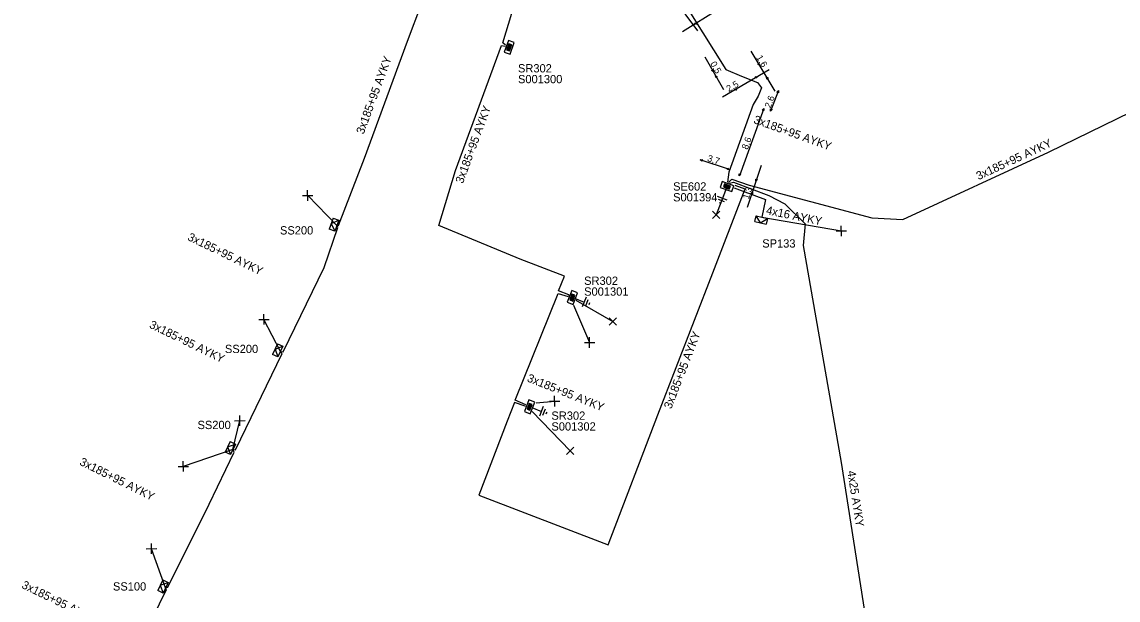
# Model space of a CAD drawing. Extents: x -762500 to -761285, y -1155006 to -1154135.
# Drawn here: x -762041.4 to -761909.8, y -1154932.9 to -1154863.6 of the extents above; entities that cross this region are included whole.
import ezdxf

# ---------------------------------------------------------------- set-up
doc = ezdxf.new("R2010")
doc.units = 0
for name, color, linetype in [('Vrstva 15', 7, 'Continuous'), ('Vrstva 28', 7, 'Continuous'), ('Vrstva 29', 7, 'Continuous'), ('Vrstva 30', 7, 'Continuous'), ('Vrstva 31', 7, 'Continuous'), ('Vrstva 33', 7, 'Continuous'), ('Vrstva 34', 7, 'Continuous'), ('Vrstva 40', 7, 'Continuous'), ('Vrstva 5', 7, 'Continuous'), ('Vrstva 59', 7, 'Continuous'), ('Vrstva 6', 7, 'Continuous')]:
    doc.layers.add(name, color=color, linetype=linetype)

msp = doc.modelspace()

# ---------------------------------------------------------------- linework, layer by layer
at = {"layer": 'Vrstva 15'}
for points in [[(-761956.7, -1154884.95), (-761957.867, -1154884.502)], [(-761956.836, -1154883.559), (-761957.284, -1154884.726)], [(-761957.036, -1154885.153), (-761957.771, -1154884.871)], [(-761957.508, -1154885.31), (-761957.627, -1154885.264)], [(-761957.383, -1154885.357), (-761957.508, -1154885.31)], [(-761975.04, -1154896.716), (-761973.873, -1154897.164)], [(-761973.649, -1154896.58), (-761974.097, -1154897.747)], [(-761973.446, -1154896.916), (-761973.729, -1154897.652)], [(-761973.29, -1154897.388), (-761973.336, -1154897.507)], [(-761973.242, -1154897.264), (-761973.29, -1154897.388)], [(-761980.171, -1154909.826), (-761979.004, -1154910.274)], [(-761978.78, -1154909.69), (-761979.228, -1154910.857)], [(-761978.577, -1154910.026), (-761978.859, -1154910.762)], [(-761978.42, -1154910.498), (-761978.466, -1154910.617)], [(-761978.373, -1154910.374), (-761978.42, -1154910.498)]]:
    msp.add_lwpolyline(points, dxfattribs=at)
at = {"layer": 'Vrstva 28'}
for points in [[(-761982.966, -1154865.772), (-761983.479, -1154867.181)], [(-761982.262, -1154866.028), (-761982.966, -1154865.772)], [(-761982.775, -1154867.438), (-761982.262, -1154866.028)], [(-761983.479, -1154867.181), (-761982.775, -1154867.438)], [(-761982.925, -1154866.195), (-761983.18, -1154866.894)], [(-761983.18, -1154866.894), (-761982.825, -1154867.023)], [(-761982.897, -1154866.255), (-761983.119, -1154866.866)], [(-761983.119, -1154866.866), (-761982.853, -1154866.963)], [(-761982.869, -1154866.316), (-761983.059, -1154866.838)], [(-761983.059, -1154866.838), (-761982.881, -1154866.902)], [(-761982.841, -1154866.377), (-761982.998, -1154866.809)], [(-761982.998, -1154866.809), (-761982.91, -1154866.842)], [(-761982.94, -1154866.787), (-761982.811, -1154866.432)], [(-761982.57, -1154866.324), (-761982.925, -1154866.195)], [(-761982.91, -1154866.842), (-761982.752, -1154866.409)], [(-761982.631, -1154866.352), (-761982.897, -1154866.255)], [(-761982.881, -1154866.902), (-761982.691, -1154866.381)], [(-761982.691, -1154866.381), (-761982.869, -1154866.316)], [(-761982.853, -1154866.963), (-761982.631, -1154866.352)], [(-761982.752, -1154866.409), (-761982.841, -1154866.377)], [(-761982.825, -1154867.023), (-761982.57, -1154866.324)], [(-761957.312, -1154882.701), (-761957.568, -1154883.406)], [(-761955.902, -1154883.214), (-761957.312, -1154882.701)], [(-761957.025, -1154883.001), (-761957.154, -1154883.356)], [(-761956.996, -1154883.061), (-761957.093, -1154883.327)], [(-761956.968, -1154883.122), (-761957.033, -1154883.299)], [(-761956.325, -1154883.255), (-761957.025, -1154883.001)], [(-761956.386, -1154883.283), (-761956.996, -1154883.061)], [(-761956.94, -1154883.182), (-761956.972, -1154883.271)], [(-761956.446, -1154883.312), (-761956.968, -1154883.122)], [(-761956.507, -1154883.34), (-761956.94, -1154883.182)], [(-761957.568, -1154883.406), (-761956.159, -1154883.919)], [(-761957.154, -1154883.356), (-761956.455, -1154883.61)], [(-761957.093, -1154883.327), (-761956.483, -1154883.55)], [(-761957.033, -1154883.299), (-761956.511, -1154883.489)], [(-761956.972, -1154883.271), (-761956.539, -1154883.429)], [(-761956.917, -1154883.241), (-761956.562, -1154883.37)], [(-761956.539, -1154883.429), (-761956.507, -1154883.34)], [(-761956.511, -1154883.489), (-761956.446, -1154883.312)], [(-761956.483, -1154883.55), (-761956.386, -1154883.283)], [(-761956.455, -1154883.61), (-761956.325, -1154883.255)], [(-761956.159, -1154883.919), (-761955.902, -1154883.214)], [(-761975.374, -1154895.797), (-761975.911, -1154897.197)], [(-761975.341, -1154896.22), (-761975.607, -1154896.915)], [(-761975.313, -1154896.282), (-761975.546, -1154896.888)], [(-761975.286, -1154896.343), (-761975.485, -1154896.861)], [(-761974.674, -1154896.065), (-761975.374, -1154895.797)], [(-761974.988, -1154896.356), (-761975.341, -1154896.22)], [(-761975.049, -1154896.383), (-761975.313, -1154896.282)], [(-761975.11, -1154896.41), (-761975.286, -1154896.343)], [(-761975.211, -1154897.466), (-761974.674, -1154896.065)], [(-761975.911, -1154897.197), (-761975.211, -1154897.466)], [(-761975.607, -1154896.915), (-761975.254, -1154897.051)], [(-761975.546, -1154896.888), (-761975.282, -1154896.99)], [(-761975.485, -1154896.861), (-761975.309, -1154896.929)], [(-761975.259, -1154896.404), (-761975.424, -1154896.834)], [(-761975.424, -1154896.834), (-761975.336, -1154896.868)], [(-761975.365, -1154896.812), (-761975.23, -1154896.459)], [(-761975.336, -1154896.868), (-761975.171, -1154896.437)], [(-761975.309, -1154896.929), (-761975.11, -1154896.41)], [(-761975.282, -1154896.99), (-761975.049, -1154896.383)], [(-761975.171, -1154896.437), (-761975.259, -1154896.404)], [(-761975.254, -1154897.051), (-761974.988, -1154896.356)], [(-761980.504, -1154908.897), (-761981.041, -1154910.297)], [(-761980.47, -1154909.321), (-761980.737, -1154910.015)], [(-761980.443, -1154909.382), (-761980.676, -1154909.988)], [(-761980.416, -1154909.443), (-761980.615, -1154909.961)], [(-761980.389, -1154909.504), (-761980.554, -1154909.934)], [(-761979.803, -1154909.165), (-761980.504, -1154908.897)], [(-761980.117, -1154909.456), (-761980.47, -1154909.321)], [(-761980.178, -1154909.483), (-761980.443, -1154909.382)], [(-761980.239, -1154909.51), (-761980.416, -1154909.443)], [(-761980.411, -1154910.09), (-761980.178, -1154909.483)], [(-761980.301, -1154909.537), (-761980.389, -1154909.504)], [(-761980.384, -1154910.151), (-761980.117, -1154909.456)], [(-761980.341, -1154910.566), (-761979.803, -1154909.165)], [(-761981.041, -1154910.297), (-761980.341, -1154910.566)], [(-761980.737, -1154910.015), (-761980.384, -1154910.151)], [(-761980.676, -1154909.988), (-761980.411, -1154910.09)], [(-761980.615, -1154909.961), (-761980.438, -1154910.029)], [(-761980.554, -1154909.934), (-761980.466, -1154909.968)], [(-761980.495, -1154909.912), (-761980.359, -1154909.559)], [(-761980.466, -1154909.968), (-761980.301, -1154909.537)], [(-761980.438, -1154910.029), (-761980.239, -1154909.51)]]:
    msp.add_lwpolyline(points, dxfattribs=at)
at = {"layer": 'Vrstva 31'}
for points in [[(-762003.997, -1154887.09), (-762004.476, -1154888.406)], [(-762003.997, -1154887.09), (-762003.34, -1154887.329), (-762003.818, -1154888.645), (-762004.476, -1154888.406)], [(-761953.392, -1154887.489), (-761953.223, -1154886.81), (-761951.864, -1154887.149), (-761952.034, -1154887.828)], [(-761952.713, -1154887.659), (-761953.223, -1154886.81)], [(-762004.237, -1154887.748), (-762003.34, -1154887.329)], [(-762004.237, -1154887.748), (-762003.818, -1154888.645)], [(-761953.392, -1154887.489), (-761952.034, -1154887.828)], [(-761952.713, -1154887.659), (-761951.864, -1154887.149)], [(-762010.678, -1154902.167), (-762011.269, -1154903.436)], [(-762010.678, -1154902.167), (-762010.043, -1154902.463), (-762010.635, -1154903.731), (-762011.269, -1154903.436)], [(-762010.974, -1154902.801), (-762010.043, -1154902.463)], [(-762010.974, -1154902.801), (-762010.635, -1154903.731)], [(-762016.378, -1154913.897), (-762016.969, -1154915.166)], [(-762016.378, -1154913.897), (-762015.743, -1154914.193), (-762016.335, -1154915.461), (-762016.969, -1154915.166)], [(-762016.674, -1154914.531), (-762015.743, -1154914.193)], [(-762016.674, -1154914.531), (-762016.335, -1154915.461)], [(-762024.458, -1154930.497), (-762025.05, -1154931.766)], [(-762024.458, -1154930.497), (-762023.824, -1154930.793), (-762024.415, -1154932.062), (-762025.05, -1154931.766)], [(-762024.754, -1154931.131), (-762023.824, -1154930.793)], [(-762024.754, -1154931.131), (-762024.415, -1154932.062)]]:
    msp.add_lwpolyline(points, dxfattribs=at)
at = {"layer": 'Vrstva 34'}
for points in [[(-762007.685, -1154884.391), (-762006.435, -1154884.369)], [(-762007.049, -1154885.005), (-762007.071, -1154883.755)], [(-761958.472, -1154886.258), (-761957.588, -1154887.142)], [(-761958.472, -1154887.142), (-761957.588, -1154886.258)], [(-761942.989, -1154889.255), (-761943.011, -1154888.005)], [(-761943.625, -1154888.641), (-761942.375, -1154888.619)], [(-762012.299, -1154899.875), (-762012.321, -1154898.625)], [(-762012.935, -1154899.261), (-762011.685, -1154899.239)], [(-761970.882, -1154899.058), (-761969.998, -1154899.942)], [(-761970.882, -1154899.942), (-761969.998, -1154899.058)], [(-761973.219, -1154902.635), (-761973.241, -1154901.385)], [(-761973.855, -1154902.021), (-761972.605, -1154901.999)], [(-761978.035, -1154909.061), (-761976.785, -1154909.039)], [(-761977.399, -1154909.675), (-761977.421, -1154908.425)], [(-762015.199, -1154912.005), (-762015.221, -1154910.755)], [(-762015.835, -1154911.391), (-762014.585, -1154911.369)], [(-761976.002, -1154914.558), (-761975.118, -1154915.442)], [(-761976.002, -1154915.442), (-761975.118, -1154914.558)], [(-762022.625, -1154916.891), (-762021.375, -1154916.869)], [(-762021.989, -1154917.505), (-762022.011, -1154916.255)], [(-762025.799, -1154927.375), (-762025.821, -1154926.125)], [(-762026.435, -1154926.761), (-762025.185, -1154926.739)]]:
    msp.add_lwpolyline(points, dxfattribs=at)
at = {"layer": 'Vrstva 40'}
for points in [[(-761963.18, -1154860.67), (-761960.29, -1154864.64)], [(-761962.07, -1154864.73), (-761957.71, -1154862.01)], [(-761950.95, -1154871.87), (-761953.85, -1154867.09)], [(-761957.12, -1154871.71), (-761959.35, -1154867.81)], [(-761951.68, -1154869.31), (-761957.27, -1154872.57)], [(-761950.55, -1154871.8), (-761951.49, -1154874.25)], [(-761952.32, -1154873.93), (-761955.25, -1154882.04)], [(-761956.42, -1154881.26), (-761959.97, -1154880.09)], [(-761952.62, -1154880.77), (-761954.31, -1154885.83)]]:
    msp.add_lwpolyline(points, dxfattribs=at)
for points in [[(-761960.368, -1154863.669), (-761960.519, -1154863.892), (-761960.633, -1154863.717)], [(-761952.809, -1154868.802), (-761953.029, -1154868.647), (-761952.852, -1154868.536)], [(-761958.359, -1154869.552), (-761958.574, -1154869.389), (-761958.393, -1154869.285)], [(-761958.111, -1154869.978), (-761957.896, -1154870.141), (-761958.077, -1154870.245)], [(-761953.402, -1154870.321), (-761953.243, -1154870.104), (-761953.135, -1154870.283)], [(-761951.981, -1154870.167), (-761951.761, -1154870.323), (-761951.938, -1154870.433)], [(-761955.537, -1154871.559), (-761955.697, -1154871.777), (-761955.804, -1154871.598)], [(-761950.549, -1154871.798), (-761950.54, -1154872.068), (-761950.736, -1154871.993)], [(-761952.319, -1154873.928), (-761952.301, -1154874.197), (-761952.499, -1154874.129)], [(-761951.491, -1154874.252), (-761951.5, -1154873.982), (-761951.305, -1154874.057)], [(-761959.972, -1154880.089), (-761959.704, -1154880.066), (-761959.768, -1154880.265)], [(-761956.417, -1154881.261), (-761956.686, -1154881.283), (-761956.622, -1154881.085)], [(-761955.251, -1154882.042), (-761955.269, -1154881.773), (-761955.072, -1154881.841)], [(-761953.251, -1154882.672), (-761953.273, -1154882.404), (-761953.074, -1154882.468)], [(-761953.679, -1154883.938), (-761953.656, -1154884.207), (-761953.855, -1154884.142)]]:
    msp.add_lwpolyline(points, close=True, dxfattribs=at)
at = {"layer": 'Vrstva 5'}
for points in [[(-761983.32, -1154866.37), (-761983.65, -1154866.06), (-761972.68, -1154829.91), (-761980.55, -1154827.13), (-761983.65, -1154827.58), (-761985.23, -1154827.47), (-762002.38, -1154820.85), (-762002.54, -1154820.55), (-762006.24, -1154819.06), (-762005.04, -1154816.5)], [(-762030.69, -1154945.3), (-762024.01, -1154931.64), (-762024.12, -1154931.43), (-762023.87, -1154931.35), (-762018.9, -1154921.41), (-762015.88, -1154915.18), (-762016.04, -1154914.83), (-762015.73, -1154914.88), (-762010.12, -1154903.35), (-762010.34, -1154903.1), (-762010, -1154903.12), (-762005.09, -1154893.02), (-762003.43, -1154888.23), (-762003.58, -1154887.99), (-762003.35, -1154888), (-762000.26, -1154879.9), (-761995.1, -1154865.87), (-761993.37, -1154861.3)], [(-761961.1, -1154862.5), (-761956.88, -1154869.27), (-761955, -1154870.05), (-761953.08, -1154870.83), (-761952.6, -1154871.45), (-761952.99, -1154872.45), (-761953.59, -1154873.47), (-761956.52, -1154881.58), (-761956.69, -1154882.79)], [(-761975.73, -1154896.39), (-761975.72, -1154896.3), (-761976.95, -1154895.81), (-761976.24, -1154894.06), (-761981.54, -1154892.01), (-761991.31, -1154888), (-761989.32, -1154881.37), (-761983.8, -1154866.39), (-761983.37, -1154866.49)], [(-761956.56, -1154882.84), (-761956.17, -1154882.41), (-761954.07, -1154883.16), (-761939.35, -1154887.07), (-761935.63, -1154887.27), (-761918.14, -1154879.2), (-761906.58, -1154873.55), (-761899.9, -1154869.73), (-761899.4, -1154869.91)], [(-761980.92, -1154909.61), (-761980.95, -1154909.66), (-761982.24, -1154909.21), (-761983.11, -1154911.45), (-761986.52, -1154920.31), (-761971, -1154926.28), (-761965.05, -1154910.71), (-761958.45, -1154893.67), (-761954.76, -1154884.1), (-761954.56, -1154883.63), (-761955.75, -1154883.18)], [(-761956.44, -1154882.89), (-761955.96, -1154882.8), (-761951.69, -1154884.37), (-761949.77, -1154885.38), (-761947.36, -1154887.8), (-761947.58, -1154890.38), (-761943.02, -1154916.39), (-761937.53, -1154951.34), (-761915.13, -1154967.16), (-761913.82, -1155000)], [(-761955.87, -1154883.48), (-761954.92, -1154883.81), (-761952.09, -1154884.88), (-761952.54, -1154886.98)], [(-761980.87, -1154909.49), (-761982.14, -1154908.93), (-761977.01, -1154896.12), (-761975.78, -1154896.51)]]:
    msp.add_lwpolyline(points, dxfattribs=at)
at = {"layer": 'Vrstva 59'}
for points in [[(-762003.58, -1154887.99), (-762007.06, -1154884.38)], [(-761956.92, -1154883.78), (-761958.03, -1154886.7)], [(-761952.54, -1154886.98), (-761943, -1154888.63)], [(-761975.14, -1154897.52), (-761973.23, -1154902.01)], [(-761974.87, -1154896.94), (-761970.44, -1154899.5)], [(-762010.34, -1154903.1), (-762012.31, -1154899.25)], [(-761979.65, -1154909.25), (-761977.41, -1154909.05)], [(-761980.1, -1154910.3), (-761975.56, -1154915)], [(-762016.04, -1154914.83), (-762015.21, -1154911.38)], [(-762016.04, -1154914.83), (-762022, -1154916.88)], [(-762024.12, -1154931.43), (-762025.81, -1154926.75)]]:
    msp.add_lwpolyline(points, dxfattribs=at)

# ---------------------------------------------------------------- texts
at = {"layer": 'Vrstva 29'}
for s, p in [('S001300', (-761981.82, -1154870.92)), ('S001394', (-761963.2, -1154885.09)), ('S001301', (-761973.88, -1154896.4)), ('S001302', (-761977.81, -1154912.58))]:
    msp.add_text(s, height=0.9943, dxfattribs=at).set_placement(p)
at = {"layer": 'Vrstva 30'}
for s, p in [('SR302', (-761981.82, -1154869.62)), ('SE602', (-761963.2, -1154883.79)), ('SR302', (-761973.88, -1154895.1)), ('SR302', (-761977.81, -1154911.28))]:
    msp.add_text(s, height=0.9943, dxfattribs=at).set_placement(p)
at = {"layer": 'Vrstva 33'}
for s, p in [('SS200', (-762010.39, -1154889.06)), ('SP133', (-761952.5, -1154890.63)), ('SS200', (-762017, -1154903.28)), ('SS200', (-762020.29, -1154912.4)), ('SS100', (-762030.44, -1154931.77))]:
    msp.add_text(s, height=0.9943, dxfattribs=at).set_placement(p)
at = {"layer": 'Vrstva 40'}
for s, rotation, p in [('0,5', 299.84318, (-761958.78, -1154868.57)), ('1,6', 301.24326, (-761953.26, -1154867.83)), ('2,5', 30.25682, (-761956.52, -1154872)), ('2,6', 68.99417, (-761951.51, -1154873.97)), ('8,6', 70.13632, (-761954.26, -1154878.94)), ('3,7', 341.71364, (-761959.16, -1154880.23)), ('1,3', 71.56401, (-761954.12, -1154884.9))]:
    msp.add_text(s, height=0.7954, rotation=rotation, dxfattribs=at).set_placement(p)
at = {"layer": 'Vrstva 6'}
for s, height, rotation, p in [('3x185+95 AYKY', 0.99429, 69.80732, (-762000.35, -1154877.1)), ('3x185+95 AYKY', 0.99429, 69.7544, (-761988.44, -1154883.02)), ('3x185+95 AYKY', 0.99429, 340.13611, (-761953.62, -1154875.67)), ('3x185+95 AYKY', 0.99428, 24.76995, (-761926.54, -1154882.55)), ('4x16 AYKY', 0.9943, 348.31767, (-761952.1, -1154886.6)), ('3x185+95 AYKY', 0.99429, 334.08326, (-762021.56, -1154889.69)), ('3x185+95 AYKY', 0.99429, 334.03251, (-762026.16, -1154900.2)), ('3x185+95 AYKY', 0.99428, 68.8261, (-761963.43, -1154910.06)), ('3x185+95 AYKY', 0.99429, 338.17777, (-761980.81, -1154906.65)), ('3x185+95 AYKY', 0.99429, 333.45109, (-762034.53, -1154916.65)), ('4x25 AYKY', 0.9943, 278.92892, (-761942.29, -1154917.46)), ('3x185+95 AYKY', 0.99428, 333.9438, (-762041.48, -1154931.42))]:
    msp.add_text(s, height=height, rotation=rotation, dxfattribs=at).set_placement(p)

doc.saveas('drawing.dxf')
